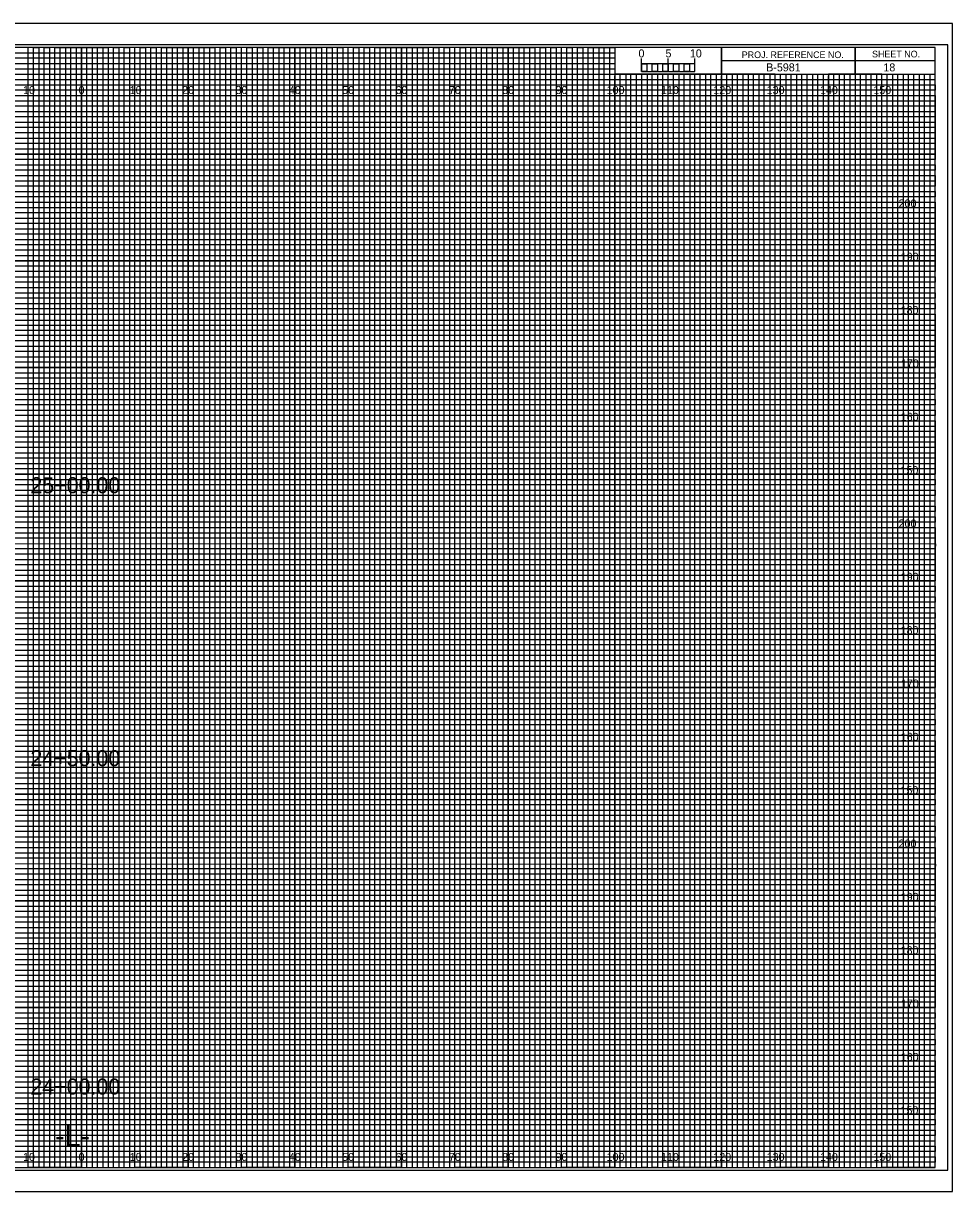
# Model space of a CAD drawing. Extents: x -13 to 323, y -5 to 4174.
# Drawn here: x 149.1 to 323.3, y 2635.5 to 2854.5 of the extents above; entities that cross this region are included whole.
import ezdxf

# ---------------------------------------------------------------- set-up
doc = ezdxf.new("R2010")
doc.units = 0
for name, color, linetype in [('Exist Cross Section Cell', 7, 'Continuous'), ('Exist XS Center Line Elevation Label', 7, 'Continuous'), ('Exist XS Ground Line', 7, 'Continuous'), ('Prop CMT Concrete Structures', 7, 'Continuous'), ('Prop CMT Guardrail Graphics', 7, 'Continuous'), ('Prop CMT Pvmt Course 1', 7, 'Continuous'), ('Prop CMT Pvmt Course 2', 7, 'Continuous'), ('Prop CMT Pvmt Course 3', 7, 'Continuous'), ('Prop CMT Pvmt Surface', 7, 'Continuous'), ('Prop CMT Shld Paved Course 1', 7, 'Continuous'), ('Prop CMT Shld Paved Course 2', 7, 'Continuous'), ('Prop CMT Shld Paved Course 3', 7, 'Continuous'), ('Prop CMT Subgrade Earthwork', 7, 'Continuous'), ('Prop XS Ditch Standard Text', 7, 'Continuous'), ('Prop XS SE Text', 7, 'Continuous'), ('Prop XS Side Slope Text', 7, 'Continuous'), ('Scratch_Level_0', 7, 'Continuous')]:
    doc.layers.add(name, color=color, linetype=linetype)

msp = doc.modelspace()

# ---------------------------------------------------------------- linework, layer by layer
at = {"layer": 'Exist XS Center Line Elevation Label'}
for points in [[(145, 2640), (155, 2640), (155, 2850), (165, 2850), (165, 2640), (175, 2640), (175, 2850), (185, 2850), (185, 2640), (195, 2640), (195, 2850), (205, 2850), (205, 2640), (215, 2640), (215, 2850), (225, 2850), (225, 2640), (235, 2640), (235, 2850), (245, 2850), (245, 2640), (255, 2640), (255, 2850), (259.93, 2850), (260, 2850), (260, 2845), (264.99, 2845), (264.99, 2640), (275, 2640), (275, 2845), (285, 2845), (285, 2640), (295, 2640), (295, 2845), (305, 2845), (305, 2640), (315, 2640), (315, 2845)], [(0, 2845), (275, 2845)], [(0, 2825), (320, 2825), (320, 2835), (0, 2835)], [(0, 2805), (320, 2805), (320, 2815), (0, 2815)], [(0, 2785), (320, 2785), (320, 2795), (0, 2795)], [(0, 2765), (320, 2765), (320, 2775), (0, 2775)], [(0, 2745), (320, 2745), (320, 2755), (0, 2755)], [(0, 2725), (320, 2725), (320, 2735), (0, 2735)], [(0, 2705), (320, 2705), (320, 2715), (0, 2715)], [(0, 2685), (320, 2685), (320, 2695), (0, 2695)], [(0, 2665), (320, 2665), (320, 2675), (0, 2675)], [(0, 2645), (320, 2645), (320, 2655), (0, 2655)]]:
    msp.add_lwpolyline(points, dxfattribs=at)
at = {"layer": 'Exist XS Ground Line'}
for p, q in [((150, 2850), (140, 2850)), ((150, 2640), (150, 2850)), ((170, 2850), (160, 2850)), ((160, 2850), (160, 2640)), ((170, 2640), (170, 2850)), ((190, 2850), (180, 2850)), ((180, 2850), (180, 2640)), ((190, 2640), (190, 2850)), ((210, 2850), (200, 2850)), ((200, 2850), (200, 2640)), ((210, 2640), (210, 2850)), ((230, 2850), (220, 2850)), ((220, 2850), (220, 2640)), ((230, 2640), (230, 2850)), ((250, 2850), (240, 2850)), ((240, 2850), (240, 2640)), ((250, 2640), (250, 2850)), ((260, 2850), (260, 2640)), ((270, 2640), (270, 2845)), ((290, 2845), (280, 2845)), ((280, 2845), (280, 2640)), ((290, 2640), (290, 2845)), ((310, 2845), (300, 2845)), ((300, 2845), (300, 2640)), ((310, 2640), (310, 2845)), ((160, 2640), (150, 2640)), ((180, 2640), (170, 2640)), ((200, 2640), (190, 2640)), ((220, 2640), (210, 2640)), ((240, 2640), (230, 2640)), ((260, 2640), (250, 2640)), ((280, 2640), (270, 2640)), ((300, 2640), (290, 2640)), ((320, 2640), (310, 2640)), ((320, 2640), (320, 2640))]:
    msp.add_line(p, q, dxfattribs=at)
for points in [[(0, 2840), (320, 2840), (320, 2830), (0, 2830)], [(0, 2820), (320, 2820), (320, 2810), (0, 2810)], [(0, 2800), (320, 2800), (320, 2790), (0, 2790)], [(0, 2780), (320, 2780), (320, 2770), (0, 2770)], [(0, 2760), (320, 2760), (320, 2750), (0, 2750)], [(0, 2740), (320, 2740), (320, 2730), (0, 2730)], [(0, 2720), (320, 2720), (320, 2710), (0, 2710)], [(0, 2700), (320, 2700), (320, 2690), (0, 2690)], [(0, 2680), (320, 2680), (320, 2670), (0, 2670)], [(0, 2660), (320, 2660), (320, 2650), (0, 2650)]]:
    msp.add_lwpolyline(points, dxfattribs=at)
at = {"layer": 'Prop CMT Pvmt Course 1'}
for p, q in [((323.3, 2854.5), (-13.4, 2854.5)), ((-13.4, 2635.5), (323.3, 2635.5))]:
    msp.add_line(p, q, dxfattribs=at)
at = {"layer": 'Prop CMT Pvmt Course 2'}
msp.add_lwpolyline([(-13.4, 2635.5), (323.3, 2635.5), (323.3, 2854.5), (-13.4, 2854.5)], close=True, dxfattribs=at)
at = {"layer": 'Prop CMT Pvmt Course 3'}
msp.add_lwpolyline([(-10.8, 2639.5), (322.4, 2639.5), (322.4, 2850.5), (-10.8, 2850.5)], close=True, dxfattribs=at)
at = {"layer": 'Prop CMT Shld Paved Course 1'}
for p, q in [((305, 2850), (305, 2845)), ((305, 2845), (305, 2850)), ((280, 2847.5), (280, 2845)), ((320, 2847.49), (280, 2847.49)), ((280, 2845), (320, 2845))]:
    msp.add_line(p, q, dxfattribs=at)
for points in [[(320, 2850), (0, 2850), (0, 2640), (320, 2640)], [(280, 2850), (260, 2850), (260, 2845.03), (280, 2845.03)], [(320, 2850), (280, 2850), (280, 2845), (320, 2845)]]:
    msp.add_lwpolyline(points, close=True, dxfattribs=at)
at = {"layer": 'Prop CMT Shld Paved Course 2'}
for p, q in [((267, 2845), (266.01, 2845)), ((266.01, 2845), (266.01, 2640)), ((267, 2640), (267, 2845)), ((269, 2845), (268, 2845)), ((268, 2845), (268, 2640)), ((269, 2640), (269, 2845)), ((266.01, 2640), (265, 2640)), ((268, 2640), (267, 2640))]:
    msp.add_line(p, q, dxfattribs=at)
for points in [[(150, 2640), (151, 2640), (151, 2850), (152, 2850), (152, 2640)], [(152, 2640), (153, 2640), (153, 2850), (154, 2850), (154, 2640)], [(155, 2640), (156, 2640), (156, 2850), (157, 2850), (157, 2640)], [(157, 2640), (158, 2640), (158, 2850), (159, 2850), (159, 2640)], [(160, 2640), (161, 2640), (161, 2850), (162, 2850), (162, 2640)], [(162, 2640), (163, 2640), (163, 2850), (164, 2850), (164, 2640)], [(165, 2640), (166, 2640), (166, 2850), (167, 2850), (167, 2640)], [(167, 2640), (168, 2640), (168, 2850), (169, 2850), (169, 2640)], [(170, 2640), (171, 2640), (171, 2850), (172, 2850), (172, 2640)], [(172, 2640), (173, 2640), (173, 2850), (174, 2850), (174, 2640)], [(175, 2640), (176, 2640), (176, 2850), (177, 2850), (177, 2640)], [(177, 2640), (178, 2640), (178, 2850), (179, 2850), (179, 2640)], [(180, 2640), (181, 2640), (181, 2850), (182, 2850), (182, 2640)], [(182, 2640), (183, 2640), (183, 2850), (184, 2850), (184, 2640)], [(185, 2640), (186, 2640), (186, 2850), (187, 2850), (187, 2640)], [(187, 2640), (188, 2640), (188, 2850), (189, 2850), (189, 2640)], [(190, 2640), (191, 2640), (191, 2850), (192, 2850), (192, 2640)], [(192, 2640), (193, 2640), (193, 2850), (194, 2850), (194, 2640)], [(195, 2640), (196, 2640), (196, 2850), (197, 2850), (197, 2640)], [(197, 2640), (198, 2640), (198, 2850), (199, 2850), (199, 2640)], [(200, 2640), (201, 2640), (201, 2850), (202, 2850), (202, 2640)], [(202, 2640), (203, 2640), (203, 2850), (204, 2850), (204, 2640)], [(205, 2640), (206, 2640), (206, 2850), (207, 2850), (207, 2640)], [(207, 2640), (208, 2640), (208, 2850), (209, 2850), (209, 2640)], [(210, 2640), (211, 2640), (211, 2850), (212, 2850), (212, 2640)], [(212, 2640), (213, 2640), (213, 2850), (214, 2850), (214, 2640)], [(215, 2640), (216, 2640), (216, 2850), (217, 2850), (217, 2640)], [(217, 2640), (218, 2640), (218, 2850), (219, 2850), (219, 2640)], [(220, 2640), (221, 2640), (221, 2850), (222, 2850), (222, 2640)], [(222, 2640), (223, 2640), (223, 2850), (224, 2850), (224, 2640)], [(225, 2640), (226, 2640), (226, 2850), (227, 2850), (227, 2640)], [(227, 2640), (228, 2640), (228, 2850), (229, 2850), (229, 2640)], [(230, 2640), (231, 2640), (231, 2850), (232, 2850), (232, 2640)], [(232, 2640), (233, 2640), (233, 2850), (234, 2850), (234, 2640)], [(235, 2640), (236, 2640), (236, 2850), (237, 2850), (237, 2640)], [(237, 2640), (238, 2640), (238, 2850), (239, 2850), (239, 2640)], [(240, 2640), (241, 2640), (241, 2850), (242, 2850), (242, 2640)], [(242, 2640), (243, 2640), (243, 2850), (244, 2850), (244, 2640)], [(245, 2640), (246, 2640), (246, 2850), (247, 2850), (247, 2640)], [(247, 2640), (248, 2640), (248, 2850), (249, 2850), (249, 2640)], [(250, 2640), (251, 2640), (251, 2850), (252, 2850), (252, 2640)], [(252, 2640), (253, 2640), (253, 2850), (254, 2850), (254, 2640)], [(255, 2640), (256, 2640), (256, 2850), (257, 2850), (257, 2640)], [(257, 2640), (258, 2640), (258, 2850), (259, 2850), (259, 2640)], [(260, 2640), (261, 2640), (261, 2845), (262.02, 2845), (262.02, 2640)], [(262, 2640), (263, 2640), (263, 2845), (263.99, 2845), (263.99, 2640)], [(270, 2640), (270.98, 2640), (270.98, 2845), (272, 2845), (272, 2640)], [(272, 2640), (273, 2640), (273, 2845), (274.05, 2845), (274.05, 2640)], [(275, 2640), (276, 2640), (276, 2845), (277, 2845), (277, 2640)], [(277, 2640), (278, 2640), (278, 2845), (279, 2845), (279, 2640)], [(280, 2640), (281, 2640), (281, 2845), (282, 2845), (282, 2640)], [(282, 2640), (283, 2640), (283, 2845), (284, 2845), (284, 2640)], [(285, 2640), (286, 2640), (286, 2845), (287, 2845), (287, 2640)], [(287, 2640), (288, 2640), (288, 2845), (289, 2845), (289, 2640)], [(290, 2640), (291, 2640), (291, 2845), (292, 2845), (292, 2640)], [(292, 2640), (293, 2640), (293, 2845), (294, 2845), (294, 2640)], [(295, 2640), (296, 2640), (296, 2845), (297, 2845), (297, 2640)], [(297, 2640), (298, 2640), (298, 2845), (299, 2845), (299, 2640)], [(300, 2640), (301, 2640), (301, 2845), (302, 2845), (302, 2640)], [(302, 2640), (303, 2640), (303, 2845), (304, 2845), (304, 2640)], [(305, 2640), (306, 2640), (306, 2845), (307, 2845), (307, 2640)], [(307, 2640), (308, 2640), (308, 2845), (309, 2845), (309, 2640)], [(310, 2640), (311, 2640), (311, 2845), (312, 2845), (312, 2640)], [(312, 2640), (313, 2640), (313, 2845), (314, 2845), (314, 2640)], [(315, 2640), (316, 2640), (316, 2845), (317, 2845), (317, 2640)], [(317, 2640), (318, 2640), (318, 2845), (319, 2845), (319, 2640)]]:
    msp.add_lwpolyline(points, dxfattribs=at)
at = {"layer": 'Prop CMT Shld Paved Course 3'}
for p, q in [((265, 2845.49), (265, 2847.9)), ((265, 2846.9), (265, 2847.9)), ((270, 2845.49), (270, 2847.9)), ((275, 2845.49), (275, 2847.9)), ((275, 2846.9), (275, 2847.9))]:
    msp.add_line(p, q, dxfattribs=at)
for points in [[(275, 2846.9), (265, 2846.9), (265, 2845.49), (275, 2845.49)], [(265, 2846.9), (266, 2846.9), (266, 2845.49), (265, 2845.49)], [(267, 2846.9), (268, 2846.9), (268, 2845.49), (267, 2845.49)], [(269, 2846.9), (270, 2846.9), (270, 2845.49), (269, 2845.49)], [(271, 2846.9), (272, 2846.9), (272, 2845.49), (271, 2845.49)], [(273, 2846.9), (274, 2846.9), (274, 2845.49), (273, 2845.49)]]:
    msp.add_lwpolyline(points, close=True, dxfattribs=at)
at = {"layer": 'Prop CMT Subgrade Earthwork'}
for p, q in [((150, 2640), (150, 2850)), ((160, 2640), (160, 2850)), ((170, 2640), (170, 2850)), ((180, 2640), (180, 2850)), ((190, 2640), (190, 2850)), ((200, 2640), (200, 2850)), ((210, 2640), (210, 2850)), ((220, 2640), (220, 2850)), ((230, 2640), (230, 2850)), ((240, 2640), (240, 2850)), ((250, 2640), (250, 2850)), ((260, 2640), (260, 2844.69)), ((270, 2640), (270, 2844.69)), ((280, 2640), (280, 2844.69)), ((290, 2640), (290, 2844.69)), ((300, 2640), (300, 2844.69)), ((310, 2640), (310, 2844.69)), ((0, 2840), (320, 2840)), ((0, 2830), (320, 2830)), ((0, 2820), (320, 2820)), ((0, 2810), (320, 2810)), ((0, 2800), (320, 2800)), ((0, 2790), (320, 2790)), ((0, 2780), (320, 2780)), ((0, 2770), (320, 2770)), ((0, 2760), (320, 2760)), ((0, 2750), (320, 2750)), ((0, 2740), (320, 2740)), ((0, 2730), (320, 2730)), ((0, 2720), (320, 2720)), ((0, 2710), (320, 2710)), ((0, 2700), (320, 2700)), ((0, 2690), (320, 2690)), ((0, 2680), (320, 2680)), ((0, 2670), (320, 2670)), ((0, 2660), (320, 2660)), ((0, 2650), (320, 2650))]:
    msp.add_line(p, q, dxfattribs=at)
at = {"layer": 'Scratch_Level_0'}
for p, q in [((0, 2849), (260, 2849)), ((260, 2847.98), (0, 2847.98)), ((0, 2847), (260, 2847)), ((260, 2849), (260, 2847.98)), ((260, 2847), (260, 2845.89)), ((260, 2845.89), (0, 2845.89)), ((0, 2844), (320, 2844))]:
    msp.add_line(p, q, dxfattribs=at)
for points in [[(0, 2843), (270, 2843), (320, 2843), (320, 2842), (0, 2842)], [(0, 2841), (320, 2841), (320, 2839), (0, 2839)], [(0, 2838), (320, 2838), (320, 2837), (0, 2836.98)], [(0, 2836), (320, 2836), (320, 2834), (0, 2834)], [(0, 2833), (320, 2833), (320, 2832), (0, 2832)], [(0, 2831), (320, 2831), (320, 2829), (0, 2829)], [(0, 2828), (320, 2828), (320, 2827), (0, 2827)], [(0, 2826), (320, 2826), (320, 2824), (0, 2824)], [(0, 2823), (320, 2823), (320, 2822), (0, 2822)], [(0, 2821), (320, 2821), (320, 2819), (0, 2819)], [(0, 2818), (320, 2818), (320, 2817), (0, 2817)], [(0, 2816), (320, 2816), (320, 2813.95), (320, 2813), (320, 2812), (0, 2812)], [(0, 2814), (320, 2814), (320, 2813), (0, 2813)], [(0, 2811), (320, 2811), (320, 2809), (0, 2809.03)], [(0, 2809.03), (320, 2809), (320, 2808), (0, 2808)], [(0, 2807), (320, 2807), (320, 2806), (0, 2806)], [(0, 2804), (320, 2804), (320, 2803), (0, 2803)], [(0, 2802), (320, 2802), (320, 2801), (0, 2801)], [(-0.07, 2798.89), (320, 2798.89), (320, 2797.88), (-0.07, 2797.88)], [(0, 2797), (320, 2797), (320, 2796), (0, 2796)], [(0, 2794), (320, 2794), (320, 2793), (0, 2793)], [(0, 2792), (320, 2792), (320, 2791), (0, 2791)], [(0, 2789), (320, 2789), (320, 2788), (0, 2788)], [(0, 2787), (320, 2787), (320, 2786), (0, 2786)], [(0, 2784), (320, 2784), (320, 2783), (0, 2783)], [(0, 2782), (320, 2782), (320, 2781), (0, 2781)], [(0, 2779), (320, 2779), (319.99, 2777.98), (0, 2778)], [(0, 2777), (320, 2777), (320, 2776), (0, 2776)], [(0, 2774), (320, 2774), (320, 2773), (0, 2773)], [(0, 2772), (320, 2772), (320, 2771), (0, 2771)], [(0, 2769), (320, 2769), (320, 2768), (0, 2768)], [(0, 2767), (320, 2767), (320, 2766), (0, 2766)], [(0, 2764), (320, 2764), (320, 2763), (0, 2763)], [(0, 2762), (320, 2762), (320, 2761), (0, 2761)], [(0, 2759), (320, 2759), (320, 2758), (0, 2758)], [(0, 2756.99), (320.07, 2756.91), (320, 2756), (0, 2756)], [(0, 2754), (320, 2754), (320, 2753), (0, 2753)], [(0, 2752), (320, 2752), (320, 2751), (0, 2751)], [(0, 2749), (320, 2749), (320, 2748), (0, 2748)], [(0, 2747), (320, 2747), (320, 2746), (0, 2746)], [(0, 2744), (320, 2744), (320, 2743), (0, 2743)], [(0, 2742), (320, 2742), (320, 2741), (0, 2741)], [(0, 2739), (320, 2739), (320, 2738), (0, 2738)], [(0, 2737), (320, 2737), (320, 2736), (0, 2736)], [(0, 2734), (320, 2734), (320, 2733), (0, 2733)], [(0, 2732), (320, 2732), (320, 2731), (0, 2731)], [(0, 2729), (320, 2729), (320, 2728), (0, 2728)], [(0, 2727), (320, 2727), (320, 2726), (0, 2726)], [(0, 2724), (320, 2724), (320, 2723), (0, 2723)], [(0, 2722), (320, 2722), (320, 2721), (0, 2721)], [(0, 2719), (320, 2719), (319.99, 2717.98), (0, 2718)], [(0, 2717), (320, 2717), (320, 2716), (0, 2716)], [(0, 2714), (320, 2714), (320, 2713), (0, 2713)], [(0, 2712), (320, 2712), (320, 2711), (0, 2711)], [(0, 2709), (320, 2709), (320, 2708), (0, 2708)], [(0, 2707), (320, 2707), (320, 2706), (0, 2706)], [(0, 2704), (320, 2704), (320, 2703), (0, 2703)], [(0, 2702), (320, 2702), (320, 2701), (0, 2701)], [(0, 2699), (320, 2699), (320, 2698), (0, 2698)], [(0, 2696.99), (320.07, 2696.91), (320, 2696), (0, 2696)], [(0, 2694), (320, 2694), (320, 2693), (0, 2693)], [(0, 2692), (320, 2692), (320, 2691), (0, 2691)], [(0, 2689), (320, 2689), (320, 2688), (0, 2688)], [(0, 2687), (320, 2687), (320, 2686), (0, 2686)], [(0, 2684), (320, 2684), (320, 2683), (0, 2683)], [(0, 2682), (320, 2682), (320, 2681), (0, 2681)], [(0, 2679), (320, 2679), (320, 2678), (0, 2678)], [(0, 2677), (320, 2677), (320, 2676), (0, 2676)], [(0, 2674), (320, 2674), (320, 2673), (0, 2673)], [(0, 2672), (320, 2672), (320, 2671), (0, 2671)], [(0, 2669), (320, 2669), (320, 2668), (0, 2668)], [(0, 2667), (320, 2667), (320, 2666), (0, 2666)], [(0, 2664), (320, 2664), (320, 2663), (0, 2663)], [(0, 2662), (320, 2662), (320, 2661), (0, 2661)], [(0, 2659), (320, 2659), (320, 2658), (0, 2658)], [(0, 2657), (320, 2657), (320, 2656), (0, 2656)], [(0, 2654), (320, 2654), (320, 2653), (0, 2653)], [(0, 2652), (320, 2652), (320, 2651), (0, 2651)], [(0, 2649), (320, 2649), (320, 2648), (0, 2648)], [(0, 2647), (320, 2647), (320, 2646), (0, 2646)], [(0, 2644), (320, 2644), (320, 2643), (0, 2643)], [(0, 2642), (320, 2642), (320, 2641), (0, 2641)]]:
    msp.add_lwpolyline(points, dxfattribs=at)

# ---------------------------------------------------------------- texts
at = {"layer": 'Exist Cross Section Cell'}
for s, p in [('10', (149.04, 2841.25)), ('0', (159.45, 2841.25)), ('0', (159.45, 2841.25)), ('10', (169.04, 2841.25)), ('20', (178.86, 2841.25)), ('30', (188.86, 2841.25)), ('40', (198.86, 2841.25)), ('50', (208.86, 2841.25)), ('60', (218.86, 2841.25)), ('70', (228.86, 2841.25)), ('80', (238.86, 2841.25)), ('90', (248.86, 2841.25)), ('100', (258.44, 2841.25)), ('110', (268.62, 2841.25)), ('120', (278.44, 2841.25)), ('130', (288.44, 2841.25)), ('140', (298.44, 2841.25)), ('150', (308.44, 2841.25)), ('10', (149.04, 2641.25)), ('0', (159.45, 2641.25)), ('0', (159.45, 2641.25)), ('10', (169.04, 2641.25)), ('20', (178.86, 2641.25)), ('30', (188.86, 2641.25)), ('40', (198.86, 2641.25)), ('50', (208.86, 2641.25)), ('60', (218.86, 2641.25)), ('70', (228.86, 2641.25)), ('80', (238.86, 2641.25)), ('90', (248.86, 2641.25)), ('100', (258.44, 2641.25)), ('110', (268.62, 2641.25)), ('120', (278.44, 2641.25)), ('130', (288.44, 2641.25)), ('140', (298.44, 2641.25)), ('150', (308.44, 2641.25))]:
    msp.add_text(s, height=1.5, dxfattribs=at).set_placement(p)
at = {"layer": 'Prop CMT Concrete Structures'}
for s, p in [('25+00.00', (150.41, 2766.42)), ('24+50.00', (150.41, 2715.26)), ('24+00.00', (150.41, 2653.7))]:
    msp.add_text(s, height=3, dxfattribs=at).set_placement(p)
at = {"layer": 'Prop CMT Guardrail Graphics'}
for s, p in [('200', (313.17, 2820)), ('190', (313.57, 2810)), ('180', (313.55, 2800)), ('170', (313.61, 2790)), ('160', (313.57, 2780)), ('150', (313.52, 2770)), ('200', (313.17, 2760)), ('190', (313.57, 2750)), ('180', (313.55, 2740)), ('170', (313.61, 2730)), ('160', (313.57, 2720)), ('150', (313.52, 2710)), ('200', (313.17, 2700)), ('190', (313.57, 2690)), ('180', (313.55, 2680)), ('170', (313.61, 2670)), ('160', (313.57, 2660)), ('150', (313.52, 2650))]:
    msp.add_text(s, height=1.5, dxfattribs=at).set_placement(p)
at = {"layer": 'Prop CMT Pvmt Surface'}
for s, p in [('5', (269.47, 2848.12)), ('10', (274.04, 2848.12))]:
    msp.add_text(s, height=1.5, dxfattribs=at).set_placement(p)
at = {"layer": 'Prop CMT Shld Paved Course 1'}
for s, p in [('PROJ. REFERENCE NO.', (283.77, 2847.99)), ('SHEET NO.', (308.19, 2848.12))]:
    msp.add_text(s, height=1.25, dxfattribs=at).set_placement(p)
at = {"layer": 'Prop CMT Shld Paved Course 3'}
msp.add_text('0', height=1.5, dxfattribs=at).set_placement((264.41, 2848.12))
at = {"layer": 'Prop XS Ditch Standard Text'}
msp.add_text('-L-', height=4, dxfattribs=at).set_placement((155.06, 2644))
at = {"layer": 'Prop XS SE Text'}
msp.add_text(' B-5981', height=1.5, dxfattribs=at).set_placement((287.79, 2845.5))
at = {"layer": 'Prop XS Side Slope Text'}
msp.add_text('18', height=1.5, dxfattribs=at).set_placement((310.32, 2845.5))

doc.saveas('drawing.dxf')
